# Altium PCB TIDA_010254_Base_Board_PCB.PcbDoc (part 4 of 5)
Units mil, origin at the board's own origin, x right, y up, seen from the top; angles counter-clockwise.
Board outline 3514.38 x 3143.81 mil, 4 copper layers (Top Layer, L2_GND1, L3_PWR1, Bottom Layer), stack 62.715 mil thick; 219 components, 146 nets, 618 pads, 2382 vias.
Unrouted connection lines stored in the file: 2280.
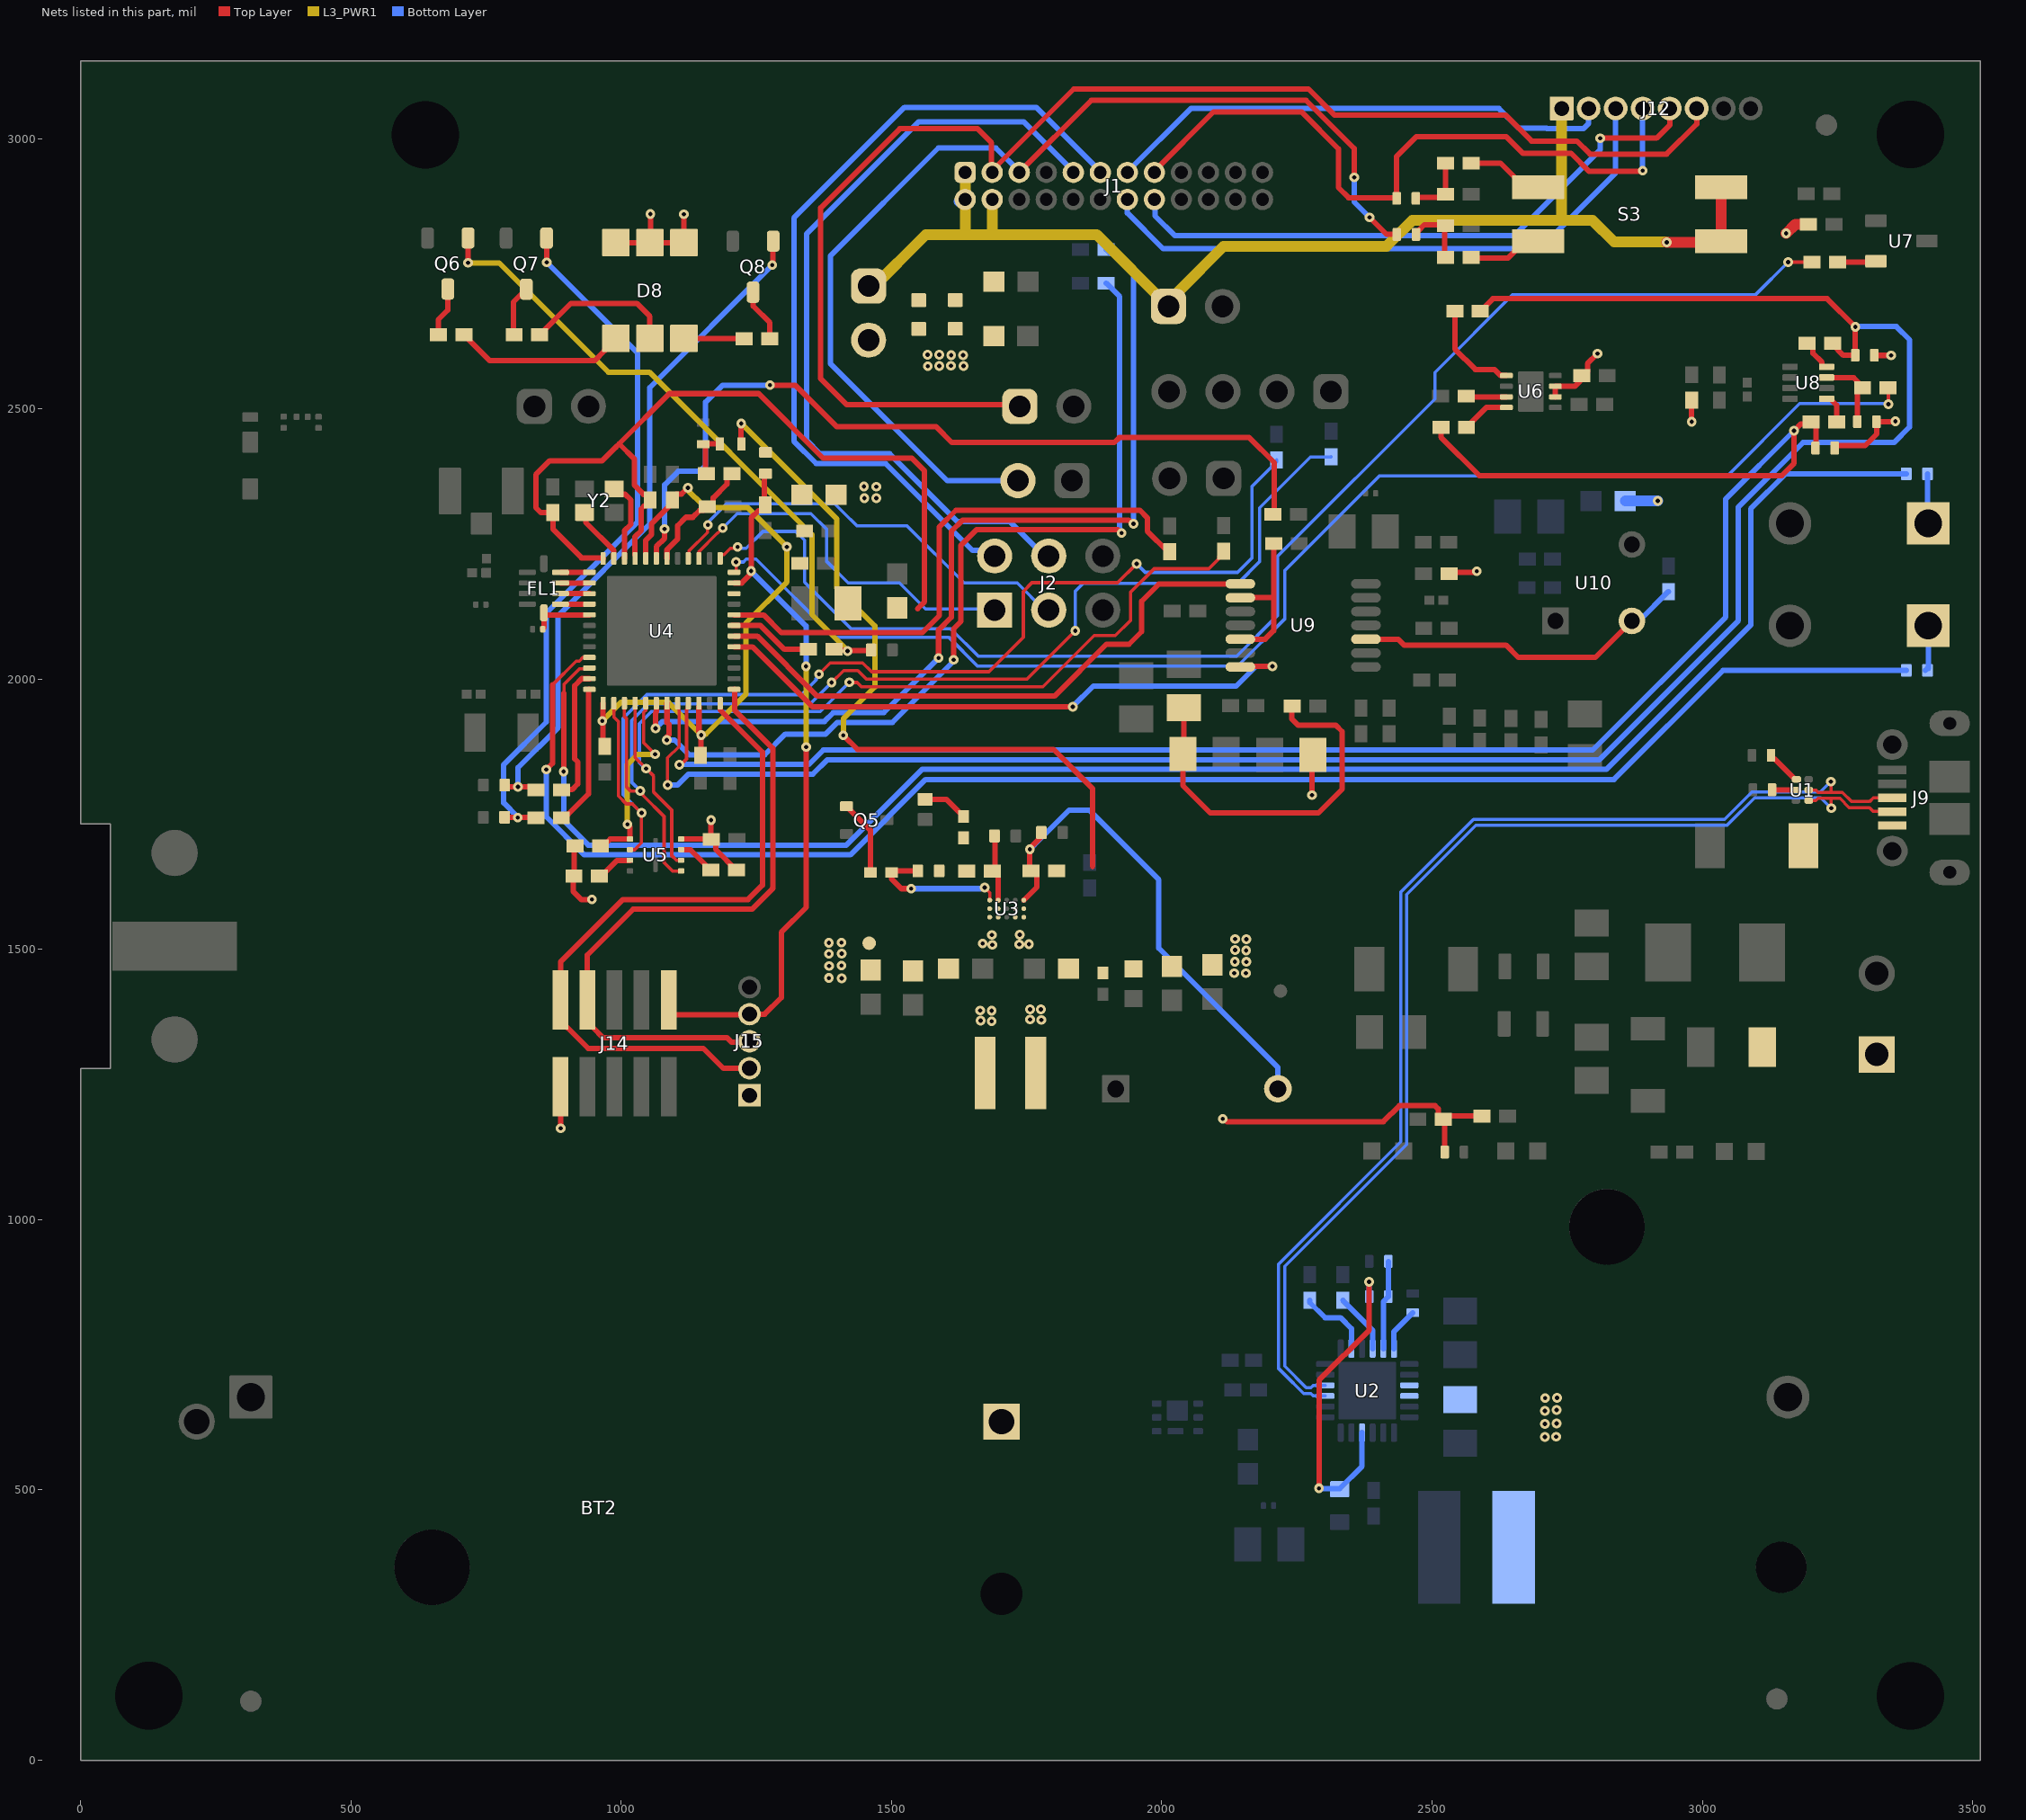
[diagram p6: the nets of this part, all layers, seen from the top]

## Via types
v1: diameter 18, hole 8, Top Layer to Bottom Layer, tented both sides, 2351 vias
v2: diameter 19.68, hole 7.87, Top Layer to Bottom Layer, 21 vias
v3: diameter 19.68, hole 11.81, Top Layer to Bottom Layer, 9 vias
v4: diameter 18, hole 8, Top Layer to Bottom Layer, tented bottom, 1 vias

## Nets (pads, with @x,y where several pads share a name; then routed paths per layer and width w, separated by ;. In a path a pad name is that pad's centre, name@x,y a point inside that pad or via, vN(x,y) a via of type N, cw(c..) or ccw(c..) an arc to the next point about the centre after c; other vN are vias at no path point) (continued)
NetD7_2: D7.2 R23.1 | length 84.5
  Top Layer w10: D7.2@1562.16,1777.8 1601.42,1777.8 R23.1@1633.43,1745.79
NetD8_1: D8.1 R27.2 | length 319.2
  Top Layer w10: R27.2@708.79,2637.27 756.82,2589.24 950.58,2589.24 969.43,2608.09 969.43,2609.84 D8.1@990.02,2630.43
NetD8_2: D8.2 R28.2 | length 278.7
  Top Layer w10: R28.2@849.08,2637.27 907.12,2695.31 1028.77,2695.31 1053.01,2671.07 D8.2@1053.01,2630.43
NetD8_3: D8.3 R29.2 | length 111.8
  Top Layer w10: D8.3@1116.01,2630.43 1116.57,2629.86 R29.2@1227.59,2629.86
NetD10_2: D10.2 J9.1
NetF1_2: F1.2 J8.1
NetFL1_6: FL1.6 U4.4 | length 55.8
  Top Layer w6: U4.4@940.97,2138.67 U4.4@943.41,2138.67
  Top Layer w10: FL1.6@887.6,2138.66 U4.4@940.97,2138.67
NetFL1_7: FL1.7 U4.3 | length 53.4
  Top Layer w10: FL1.7@887.6,2158.34 U4.3@940.97,2158.36
NetFL1_8: FL1.8 U4.2 | length 53.4
  Top Layer w10: FL1.8@887.62,2178.04 U4.2@940.97,2178.04
NetFL1_9: FL1.9 U4.1 | length 53.4
  Top Layer w10: FL1.9@887.6,2197.71 U4.1@940.97,2197.73
NetL4_1: L4.1 U3.B2 U3.B3
  other v1: 1776.93,1369.56 1756.18,1370.51 1756.58,1389.24 1776.26,1389.1 1736.28,1509.25 1754.3,1509.68 1737.07,1527.23
NetL4_2: L4.2 U3.D2 U3.D3
  other v1: 1685.27,1367.02 1664.69,1368.14 1663.75,1387.04 1685.08,1386.47 1686.49,1508.55 1668.69,1510.95 1685.49,1526.78
NetQ5_1: Q5.1 R24.2 | length 140.8
  Top Layer w10: Q5.1@1416.69,1764.8 1460.85,1720.64 R24.2@1460.85,1642.32
NetQ6_1: Q6.1 R25.2 R26.1 | length 1191.1
  Top Layer w6: v1@716.47,2770.4 v1(716.7,2770.17)
  Top Layer w10: v1@716.47,2770.4 Q6.1@716.47,2816.21 ; R25.2@1393.76,2055.14 1394.99,2053.91 1414.54,2053.91 1416.34,2052.11 v1(1418.51,2052.11) ; v1@1421.64,2052.94 R26.1@1455.36,2052.94
  L3_PWR1 w10: v1(716.7,2770.17) 774,2770.17 976.14,2568.03 1052.04,2568.03 1352.96,2267.12 1352.96,2119.06 v1@1418.37,2053.64
NetQ6_3: Q6.3 R27.1 | length 91.7
  Top Layer w10: R27.1@661.55,2637.27 661.55,2664.98 679.07,2682.5 Q6.3@679.07,2721.72
NetQ7_1: Q7.1 R30.2 R31.1 | length 1312.9
  Top Layer w6: R31.1@788.49,1745.06 R31.1@789.11,1744.45 ; v1@808,1744.45 v1(808.65,1743.8) v1@809.27,1744.41 ; R30.2@841.05,1744.41 R30.2@841.91,1743.55 ; Q7.1@861.85,2815.91 Q7.1@862.02,2815.73 ; v1@862.02,2771.31 v1(862.2,2771.13)
  Top Layer w10: R31.1@789.11,1744.45 v1@808,1744.45 ; v1@809.27,1744.41 R30.2@841.05,1744.41 ; v1@862.02,2771.31 Q7.1@862.02,2815.73
  Bottom Layer w6: v1(808.65,1743.8) v1@808.65,1744.83
  Bottom Layer w10: v1@808.65,1744.83 782.48,1771 782.48,1841.79 861.28,1920.59 861.28,2122.26 1030.38,2291.36 1030.38,2602.96 v1@860.17,2773.16
NetQ7_3: Q7.3 R28.1 | length 94.7
  Top Layer w10: R28.1@801.84,2637.27 800.46,2638.65 800.46,2697.44 Q7.3@824.44,2721.42
NetQ8_1: Q8.1 R32.2 R33.1 | length 1255.1
  Top Layer w6: R33.1@784.56,1808.84 784.56,1807.61 R33.1@791.27,1800.9
  Top Layer w10: R33.1@791.27,1800.9 v1(808.87,1800.9) R32.2@831.13,1800.9 ; v1(1279.3,2766.14) 1280.23,2767.08 1280.23,2809.15 Q8.1@1281.16,2810.08
  Bottom Layer w10: v1(808.87,1800.9) 808.87,1836.3 883.08,1910.5 883.08,2117.45 1052.99,2287.36 1052.99,2539.53 v1@1279.3,2765.84
NetQ8_3: Q8.3 R29.1 | length 104.6
  Top Layer w10: Q8.3@1244.18,2721.74 1244.18,2690 1274.83,2659.35 R29.1@1274.83,2629.86
NetR1_2: R1.2 U1.1 | length 67.9
  Top Layer w10: R1.2@3127.1,1859.06 3127.1,1855.12 3129.97,1852.25 3133.91,1852.25 3170.2,1815.96 3170.2,1815.56 3171.1,1814.65 U1.1@3174.06,1814.65
NetR2_2: R2.2 U1.2 | length 44.3
  Top Layer w10: R2.2@3128.98,1795.39 3129.41,1794.97 U1.2@3173.07,1794.97
NetR5_2: R5.2 U2.8 | length 137.9
  Bottom Layer w10: R5.2@2273.73,850.77 2273.73,846.83 2301.95,818.61 2330.54,818.61 2350.67,798.48 U2.8@2350.67,761.52
NetR10_2: R10.2 U2.12 | length 81
  Bottom Layer w10: U2.12@2429.41,761.52 2429.41,793.02 R10.2@2464.41,828.02
NetR13_2: R13.2 U2.10 | length 112.1
  Bottom Layer w10: R13.2@2334.9,850.77 2390.04,795.63 U2.10@2390.04,761.52
NetR14_1: R14.1 R16.2 U2.11 | length 165.2
  Bottom Layer w10: U2.11@2409.72,761.52 2409.72,848.28 R14.1@2419.1,857.67 R16.2@2419.1,922.83
NetR19_1: R19.1 R22.2 U3.D1 | length 122.1
  Top Layer w10: R22.2@1691.81,1708.61 1691.81,1648.03 1689.03,1645.25 1697.44,1636.85 U3.D1@1697.44,1591.15
NetR20_1: R20.1 R21.1 SW1.2 U3.A1 | length 943
  Top Layer w10: U3.A1@1744.68,1591.15 1768.75,1615.21 1768.75,1638.44 1761.94,1645.25 R20.1@1758.13,1645.25 ; R20.1@1755.24,1645.25 1755.24,1686.46 R21.1@1777.39,1708.61
  Bottom Layer w10: v1(1756.02,1685.11) 1763.61,1692.69 1828.62,1757.7 1865.65,1757.7 1994.34,1629.02 1994.34,1502.16 2214.77,1281.72 SW1.2@2214.77,1242.23
NetR34_1: R34.1 R35.2 R36.2 | length 87.9
  Top Layer w6: R36.2@1151.61,2434.44 R36.2@1152.59,2435.42
  Top Layer w10: R36.2@1152.59,2435.42 R34.1@1182.65,2435.42 ; R35.2@1156.13,2372.95 R36.2@1156.13,2429.4
NetR39_2: R39.2 S1.1 | length 84
  Bottom Layer w10: R39.2@3412.59,2016.21 R39.2@3415.7,2019.32 ; R39.2@3417.91,2019.32 S1.1@3417.91,2098.89
NetR40_2: R40.2 S2.1 | length 92.3
  Bottom Layer w10: R40.2@3416.6,2379.92 3416.6,2289.46 S2.1@3417.91,2288.15
NetR43_1: R43.1 U6.3 | length 74.8
  Top Layer w10: R43.1@2563.22,2523.63 2564.61,2522.24 U6.3@2637.49,2522.24
NetR44_2: R44.2 U7.2 | length 71.6
  Top Layer w10: R44.2@3250.05,2771.61 3319.4,2771.61 U7.2@3321,2773.21
NetR45_1: R45.1 R48.1 U8.7 | length 143.9
  Top Layer w10: U8.7@3228.4,2557.71 3279.94,2557.71 3296.49,2541.16 3286.69,2531.36 R45.1@3286.69,2476.3
NetR50_1: R50.1 U5.3 | length 59
  Top Layer w10: R50.1@967.45,1639.95 992.3,1664.8 U5.3@1016.17,1664.8
NetR51_1: R51.1 U5.7 | length 70.7
  Top Layer w10: U5.7@1110.66,1684.48 1128.2,1684.48 R51.1@1165.81,1646.88
NetR55_1: R55.1 R60.2 R61.2 | length 718.3
  Top Layer w10: R61.2@2040.87,1953.63 2040.87,1868.66 2040.87,1863.23 R55.1@2038.91,1861.26 2038.91,1803.38 2089.72,1752.57 2289.82,1752.57 2333.56,1796.3 2333.56,1903.16 2321.68,1915.04 2251.87,1915.04 2240.13,1926.77 R60.2@2240.13,1950.1
NetR57_2: R57.2 U9.9 U9.12 | length 290.4
  Top Layer w10: U9.12@2145.3,2073.94 2191.15,2073.94 2206.95,2089.73 R57.2@2206.95,2250.92 ; U9.9@2145.3,2150.71 2205.46,2150.71 2206.05,2151.29
NetR59_2: R59.2 U9.3 U10.2 | length 624
  Top Layer w10: U9.3@2377.59,2073.94 2437.37,2073.94 2448.18,2063.13 2636.69,2063.13 2659.39,2040.43 2802.2,2040.43 U10.2@2869.5,2107.73
  Bottom Layer w10: U10.2@2869.5,2107.73 2883.03,2107.73 R59.2@2937.32,2162.02
NetR66_1: R66.1 R70.1 R75.2 | length 117.8
  Top Layer w10: R66.1@2467.3,2891.2 2519.22,2891.2 R75.2@2525.21,2897.2 R70.1@2525.21,2954.64
NetR67_2: R67.2 U4.18 | length 1746.1
  Top Layer w10: v1(1063.3,1908.95) 1063.3,1937.65 1064.99,1939.35 U4.18@1064.99,1955.6 ; v1(1587.07,2039.27) 1587.07,2090.88 1610.63,2114.44 1610.63,2273.23 1631.76,2294.36 1938.81,2294.36 v1@1945.53,2287.65
  Bottom Layer w10: v1(1063.3,1908.95) 1076.19,1921.84 1375.88,1921.84 1392.14,1938.1 1485.9,1938.1 v1(1587.07,2039.27) ; R67.2@1897.02,2795.01 1903.83,2788.2 1908.04,2788.2 1947.69,2748.55 v1(1947.69,2287.65)
NetR68_2: R68.2 U4.19 | length 1690
  Top Layer w10: v1(1084.42,1887.56) 1084.42,1893.22 1088.17,1896.97 1088.17,1916.46 1084.67,1919.95 U4.19@1084.67,1955.6 ; v1(1614.85,2035.78) 1614.85,2093.21 1628.63,2106.99 1628.63,2247.92 1657.08,2276.36 1918.86,2276.36 1920.3,2275.59 v1(1925.52,2270.36)
  Bottom Layer w10: v1(1084.42,1887.56) 1098.45,1887.56 1125.7,1860.3 1265.59,1860.3 1303.68,1898.39 1377.98,1898.39 1399.69,1920.1 1501.84,1920.1 1614.85,2033.11 v1(1614.85,2035.78) ; R68.2@1897.02,2732.64 1922.02,2707.64 1922.02,2273.87 v1(1925.52,2270.36)
NetR70_2: R70.2 S3.1 | length 149.7
  Top Layer w10: R70.2@2565.52,2954.85 2626.33,2954.85 2653.34,2927.84 2653.34,2927.29 2670.59,2910.04 S3.1@2696.38,2910.04
NetR71_2: R71.2 U6.4 | length 89.1
  Top Layer w10: R71.2@2563.57,2465.78 2600.36,2502.56 U6.4@2637.49,2502.56
NetR72_2: R72.2 U6.1 | length 185.9
  Top Layer w10: R72.2@2542,2680.9 2542,2610.87 2579.95,2572.91 2615.34,2572.91 2626.64,2561.61 U6.1@2637.49,2561.61
NetR73_1: R73.1 U8.5 | length 45.1
  Top Layer w10: U8.5@3238.62,2516.84 3248.39,2507.08 R73.1@3248.39,2475.81
NetR74_1: R74.1 U8.8 | length 65.6
  Top Layer w10: R74.1@3193.72,2621.55 3197.65,2621.55 3204.46,2614.73 3204.46,2602.95 3221.18,2586.23 3221.18,2578.73 3222.08,2577.83 U8.8@3229.89,2577.83
NetR76_1: R76.1 R77.1 R78.2 | length 122.4
  Top Layer w10: R76.1@2469.69,2824.7 2469.69,2826.14 2473.17,2829.62 2474.61,2829.62 2485.53,2840.53 R78.2@2524.86,2840.53 ; R77.1@2524.86,2780.11 2523.56,2781.41 2523.56,2837.53 R78.2@2524.86,2838.84
NetR77_2: R77.2 S3.2 | length 168.3
  Top Layer w10: R77.2@2566.96,2779.41 2640.63,2779.41 2653.34,2792.12 2653.34,2792.8 S3.2@2670.59,2810.04 ; S3.2@2670.59,2810.04 S3.2@2696.38,2810.04 S3.2@2670.59,2810.04
NetU4_46: U4.46 Y2.3 | length 152.4
  Top Layer w10: Y2.3@987.08,2351.88 996.78,2342.18 1007.3,2342.18 1017.8,2331.68 1017.8,2286.45 1005.93,2274.59 U4.46@1005.93,2223.32
NetU4_47: U4.47 Y2.1 | length 121.9
  Top Layer w6: Y2.1@931.96,2308.57 Y2.1@942,2298.53
  Top Layer w10: Y2.1@931.96,2308.57 934.46,2306.07 934.46,2289.77 986.25,2237.98 U4.47@986.25,2223.32
OPT_INT: R48.2 U4.36 | length 2523.8
  Top Layer w6: U4.36@1208.69,2197.73 1210.87,2197.73 1212.6,2199.45 v1(1212.6,2216.76) ; R48.2@3343.73,2541.16 3344.25,2540.65 v1(3344.25,2508.9)
  Bottom Layer w6: v1(1212.6,2216.76) 1225.84,2216.76 1231.04,2221.96 1249.27,2221.96 1393.52,2077.7 1605.62,2077.7 1659.01,2024.31 2140.13,2024.31 2227.82,2112 2227.82,2201.34 2402.19,2375.71 3045.93,2375.71 3179.9,2509.68 3343.47,2509.68 v1(3344.25,2508.9)
PIR_OUT_HI: U4.29 U9.14 | length 1133.5
  Top Layer w10: U4.29@1208.69,2059.93 1242.55,2059.93 1353.43,1949.05 v1(1835.13,1949.05) ; U9.14@2145.3,2022.76 2146.27,2023.73 v1(2204.41,2023.73) v1@2205.38,2024.7
  Bottom Layer w10: v1(1835.13,1949.05) 1873.23,1987.15 2137.44,1987.15 2174.02,2023.73 v1(2204.41,2023.73)
PIR_OUT_LO: U4.30 U9.8 | length 1101.5
  Top Layer w6: U9.8@2144.64,2175.64 U9.8@2145.3,2176.3
  Top Layer w10: U4.30@1208.69,2079.62 1251.74,2079.62 1362.66,1968.7 1801.62,1968.7 1897.41,2064.49 1939.23,2064.49 1962.59,2087.84 1962.59,2138.57 1962.6,2144.08 1994.16,2175.64 U9.8@2144.64,2175.64
PIR_SIGNAL_ADC: R54.2 U4.43 | length 1578.8
  Top Layer w10: U4.43@1064.99,2223.32 1064.99,2245.29 1080.2,2260.5 v1(1080.2,2277.79) ; v1(1275.01,2543.94) 1321.59,2543.94 1398.8,2466.73 1582.67,2466.73 1611.59,2437.81 1911.94,2437.81 1921.16,2447.04 2161.61,2447.04 2208.09,2400.56 R54.2@2208.09,2303.89
  Bottom Layer w10: v1@1080.37,2277.96 1080.37,2359.62 1105.22,2384.46 1145.14,2384.46 1156.17,2395.49 1156.17,2512.58 1187.52,2543.94 v1(1275.01,2543.94)
PMIC_CLKOUT_LIN_PHY_TX_SOP1: J1.5 J7.2 R76.2 | length 2001.5
  Top Layer w10: J1.5@1736.28,2937.4 1869.81,3070.92 2266.75,3070.92 2356.03,2981.65 v1(2356.03,2928.43) ; v1(2384.33,2854.38) 2415.9,2822.81 R76.2@2434.87,2822.81
  Bottom Layer w10: J7.2@1733.87,2367.31 1603.11,2367.31 1415.42,2555 1386.76,2583.67 1386.76,2782.79 1586.69,2982.72 1692.95,2982.72 J1.5@1736.76,2938.92 ; v1(2356.03,2928.43) 2356.03,2882.68 v1(2384.33,2854.38)
RADAR_3V3: C2.1 FB3.2 FB4.2 J1.1 J1.2 J1.4 J3.1 J4.1 J12.1 S3.3 S3.4 | length 2277.6
  Top Layer w20: v1@2933.91,2808.34 3033.26,2808.34 S3.3@3034.96,2810.04 S3.4@3034.96,2910.04 ; S3.4@3033.7,2910.45 S3.4@3034.1,2910.04
  L3_PWR1 w20: J4.1@1461.08,2719.88 1563.62,2822.42 1636.38,2822.42 ; J1.1@1636.28,2937.4 J1.2@1636.28,2887.4 1636.28,2822.52 1636.38,2822.42 ; J1.4@1686.28,2887.4 1686.28,2823.49 1685.21,2822.42 ; J12.1@2739.56,3055.87 2739.56,2850.47 2738.09,2849 ; v1@2933.61,2808.58 2837.08,2808.58 2796.66,2849 2738.09,2849 ; 1636.38,2822.42 1685.21,2822.42 ; 1685.21,2822.42 1879.49,2822.42 J3.1@2012.34,2689.57 2030.97,2708.2 2030.97,2717.57 2114.35,2800.95 2415.58,2800.95 2463.64,2849 2738.09,2849
  Bottom Layer w10: J3.1@2012.34,2689.57 J3.1@2023.58,2678.33
  Bottom Layer w20: J1.2@1624.63,2883.69 1632.57,2883.69 J1.2@1636.28,2887.4
  other v1: 2933.88,2808.31
RADAR_NRST: J1.3 J12.6 J16.1 | length 2603.4
  Top Layer w10: J1.3@1685.16,2944.57 1685.16,2992.35 1659.29,3018.23 1515.37,3018.23 1368.97,2871.83 1368.97,2555.89 1417.1,2507.77 1734.36,2507.77 J16.1@1737.33,2504.8 ; J1.3@1689.82,2944.57 1837.1,3091.84 2271.29,3091.84 2319.27,3043.86 2635.69,3043.86 2683.99,2995.56 2767.84,2995.56 2792.06,2971.34 2933.96,2971.34 2989.56,3026.93 J12.6@2989.56,3055.87
REG_PG: R24.1 R49.2 U3.E1 | length 268.9
  Top Layer w6: v1(1672.25,1614.47) 1681.69,1605.03 U3.E1@1681.69,1591.15
  Top Layer w10: v1(1536.3,1612.44) 1518.07,1612.44 1500.53,1629.98 1500.53,1642.64 1503.15,1645.25 R49.2@1548.67,1645.25
  Bottom Layer w10: v1(1536.3,1612.44) 1573.66,1612.44 1664.57,1612.44 1665.07,1612.94 1670.72,1612.94 v1(1672.25,1614.47)
REGN: C8.1 R14.2 U2.22 | length 606.9
  Top Layer w10: v1(2290.85,503.02) 2290.85,703.12 2383.67,795.94 v1(2383.67,885.02)
  Bottom Layer w10: v1(2290.85,503.02) 2291.43,502.44 2329.1,502.44 2370.35,543.7 U2.22@2370.35,606 ; R14.2@2383.67,857.67 v1(2383.67,885.02)
RX_TX: C27.2 FL1.5 U4.5 | length 115.6
  Top Layer w6: FL1.5@856.89,2122.71 FL1.5@860.62,2118.99
  Top Layer w10: C27.2@854.81,2093.33 857.34,2095.87 FL1.5@857.34,2122.26 ; FL1.5@860.62,2118.99 U4.5@940.97,2118.99
SPI_CS: R65.2 U4.32 | length 1055.4
  Top Layer w10: U4.32@1208.69,2118.99 1263.29,2118.99 1296.14,2086.13 1556.86,2086.13 1588.48,2117.74 1588.48,2281.75 1619.09,2312.36 1959.6,2312.36 1973.33,2298.64 1973.33,2273.96 2011.44,2235.84 R65.2@2014.57,2235.84
SYS_POWER: BT2.1 C4.1 C12.1 C13.1 C14.1 C43.1 C44.1 L3.2 R7.1 R15.2 R20.2 R34.2 R52.1 U2.15 U2.16 U3.A2 U3.A3 | length 1955.3
  Top Layer w6: R34.2@1221.71,2443.27 R34.2@1222.05,2442.93 ; v1@1221.71,2472.8 v1(1222.05,2473.14)
  Top Layer w10: R34.2@1221.71,2443.27 v1@1221.71,2472.8 ; v1(1410.85,1896.1) 1437.14,1869.81 1799.77,1869.81 1872.22,1797.35 1872.22,1653.35 ; v1(2112.84,1186.64) 2115,1186.64 2120.3,1181.34 2409.87,1181.34 2439.44,1210.91 2505.62,1210.91 2511.48,1205.05 2511.48,1192.59 2515.58,1188.49 R7.1@2522.25,1188.49 ; R52.1@2523.52,1125.11 R7.1@2523.52,1190.76 ; R7.1@2523.52,1191.59 2531.94,1191.59 R15.2@2592.45,1191.59
  L3_PWR1 w10: v1(1222.05,2473.14) 1398.94,2296.25 1398.94,2168.78 1469.15,2098.56 1469.15,1985.46 1410.85,1927.16 v1(1410.85,1896.1)
  other v1: 2708.79,597.96 2729.29,598.55 2708.79,622.32 2730.48,623.21 2708.79,646.38 2730.48,647.87 2709.09,670.15 2731.08,670.45 2133.85,1455.95 2155.62,1455.95 2135.26,1477.25 2156.56,1477.02 2135.72,1499.03 2156.09,1498.32 2135.72,1519.16 2156.56,1518.69
SYS_POWER_ADC: C28.1 R35.1 U4.42 | length 222
  Top Layer w10: U4.42@1084.67,2223.32 1084.67,2239.52 1102.37,2257.21 1102.37,2257.39 1104.2,2259.23 1104.2,2283.99 1119.7,2299.49 1132.27,2299.49 1145.17,2312.39 1152.63,2312.39 C28.1@1159.44,2319.2 1163.38,2319.2 1170.19,2326.01 1170.19,2335.44 1195.38,2360.63 1195.38,2373.36 1202.19,2380.17 R35.1@1204.62,2380.17
USB_D_N: J9.2 U1.4 U2.4 | length 2108.8
  Top Layer w5.8: U1.4@3196.7,1775.28 3209.97,1775.28 3214.31,1779.62 3238.23,1779.62 ; v1@3238.23,1761.26 3238.23,1779.62 ; J9.2@3348.49,1755.17 3316.52,1755.17 3309.22,1762.47 3271.66,1762.47 3254.5,1779.62 3238.23,1779.62
  Bottom Layer w5.8: U2.4@2302.44,693.6 2280.31,693.6 2275.96,689.26 2267.05,689.26 2227.29,729.02 2227.29,913.53 2453.21,1139.46 2453.21,1601.69 2581.04,1729.52 3045.64,1729.52 3048.86,1732.74 3096.47,1780.35 3219.17,1780.35 v1(3238.32,1761.2)
USB_D_P: J9.3 U1.5 U2.3 | length 2144.8
  Top Layer w5.8: U1.5@3196.7,1794.97 3209.97,1794.97 3214.31,1790.62 3238,1790.62 ; v1@3238,1809.32 3238,1790.62 ; J9.3@3348.49,1780.77 3316.52,1780.77 3309.22,1773.47 3276.21,1773.47 3259.06,1790.62 3238,1790.62
  Bottom Layer w5.8: U2.3@2302.44,673.92 2280.31,673.92 2275.96,678.26 2262.49,678.26 2225.37,715.39 2216.29,724.47 2216.29,918.09 2442.21,1144.01 2442.21,1606.25 2576.48,1740.52 3041.08,1740.52 3091.91,1791.35 3218.44,1791.35 v1(3237.59,1810.5)
VCC_3V3: C1.1 C15.1 C16.1 C17.1 C38.1 D8.4 D8.5 D8.6 FB3.1 FB4.1 J4.2 J14.1 J15.1 L6.1 R3.2 R6.2 R19.2 R23.2 R38.2 R41.2 R42.2 R45.2 R46.2 R47.2 R49.1 R50.2 R51.2 R58.1 R63.1 TP1.1 U3.E2 U3.E3 U5.8 U6.6 U6.7 | length 1181.9
  Top Layer w10: v1@887.9,1169.05 J14.1@887.9,1209.64 ; R38.2@914.32,1691.4 912.5,1689.59 R50.2@912.5,1635.68 911.64,1634.82 911.64,1606.8 925.98,1592.46 v1(945.81,1592.46) ; D8.6@990.02,2807.59 D8.5@1053.01,2807.59 ; v1(1053.94,2860.28) 1053.94,2808.52 D8.5@1053.01,2807.59 ; U5.8@1110.66,1704.17 1166.03,1704.17 C38.1@1166.17,1704.03 ; v1(1115.87,2860) 1115.87,2807.73 D8.4@1116.01,2807.59 D8.5@1053.01,2807.59 ; v1@1166.17,1739.09 C38.1@1166.17,1704.03 ; C38.1@1166.59,1703.61 C38.1@1166.17,1704.03 ; C38.1@1168.16,1703.61 1174.97,1696.8 1174.97,1684.95 R51.2@1213.05,1646.88 ; v1(2277.93,1785.54) 2277.93,1858.61 R6.2@2279.51,1860.2 ; R63.1@2523.54,2197.89 2581.02,2197.89 v1(2582.74,2199.61) ; U6.6@2728.04,2522.24 U6.7@2728.04,2541.93 ; U6.7@2728.2,2541.77 2764.11,2541.77 2773.17,2550.84 2773.17,2564.93 2783.97,2564.93 2787.47,2568.43 2787.47,2583.66 v1(2806.02,2602.22) ; v1(2980.19,2476.42) R58.1@2980.19,2515.92 2983.05,2518.78 R58.1@2983.25,2518.78 ; R46.2@3244.12,2432.11 3301.09,2432.11 3322.62,2453.64 R45.2@3322.62,2475.8 ; R47.2@3318.15,2599.26 3318.48,2598.93 v1(3349.11,2598.93) ; R45.2@3322.12,2476.3 3355.94,2476.3 v1@3357,2477.36
  Top Layer w20: v1@3154.94,2824.53 3171.91,2841.49 R42.2@3196.29,2841.49
  Bottom Layer w10: J4.2@1457.5,2627.24 J4.2@1471.17,2627.24 ; R3.2@2857.22,2329.36 R3.2@2857.86,2330.01
  Bottom Layer w20: R3.2@2857.86,2330.01 v1(2917.7,2330.01)
  other v1: 887.87,1169.02 1384.22,1447.08 1408,1446.71 1384.59,1469.38 1407.45,1470.31 1384.22,1491.88 1407.63,1492.06 1384.22,1512.34 1407.45,1512.53 1166.2,1739.12 1449.95,2334.81 1471.93,2334.95 1471.82,2355.93 1449.07,2356.48 3357.2,2477 1567.1,2578.93 1588.54,2579.48 1609.89,2579.66 1633.1,2579.3 1610.24,2599.22 1632.39,2599.14 1588.27,2600.03 1566.84,2600.38 3154.95,2824.99
VDDR: C23.1 C24.1 C25.1 L5.2 U4.45 U4.48 | length 1586.3
  Top Layer w10: C25.1@873.56,2308.29 851.03,2308.29 841.97,2317.35 841.97,2378.19 867.86,2404.08 964.71,2404.08 989.85,2429.22 996.05,2435.42 ; C25.1@873.92,2308.29 873.92,2277.08 926.41,2224.59 965.29,2224.59 U4.48@966.56,2223.32 ; U4.45@1025.58,2230.13 1025.58,2263.56 1036.77,2274.75 1036.77,2314.83 1042.86,2320.92 1046.79,2320.92 1053.6,2327.73 C24.1@1053.6,2331.67 ; C24.1@1054.15,2335.05 1047.3,2341.9 1041.41,2341.9 1024.51,2358.8 1024.51,2406.97 996.05,2435.42 ; 1548.36,2130.52 1561.23,2143.4 1561.23,2385.2 1537.91,2408.52 1373.79,2408.52 1254.07,2528.23 1088.86,2528.23 996.05,2435.42
VDDS: C18.1 C19.1 C20.1 C21.1 C22.1 L6.2 R37.2 U4.13 U4.22 U4.34 U4.44 | length 1207.2
  Top Layer w6: C18.1@964.16,1880.67 C18.1@969.23,1875.6
  Top Layer w10: U4.13@966.29,1955.33 966.29,1924.15 v1(964.93,1922.8) 966.47,1921.27 966.47,1880.77 C18.1@966.56,1880.67 ; U4.44@1045.3,2223.32 1045.3,2256.81 1056.2,2267.71 1056.2,2287.73 1087.76,2319.28 1087.76,2320.76 1089.26,2322.26 C20.1@1090.74,2322.26 ; C20.1@1094.57,2331.51 1094.57,2335.45 1101.38,2342.26 1111.55,2342.26 v1(1123.36,2354.06) ; U4.22@1143.73,1948.79 1143.73,1902.77 1147.75,1898.74 v1(1147.75,1896.58) ; C19.1@1144.51,1860.11 1147.14,1862.74 1147.14,1895.16 v1@1148.65,1896.67
  L3_PWR1 w10: v1(964.93,1922.8) 999.16,1957.03 1087.31,1957.03 v1(1147.75,1896.58) 1149.28,1898.11 1156.68,1898.11 1230.38,1971.81 1230.38,2103.69 1306.51,2179.82 v1(1306.51,2244.75) 1233.69,2317.58 1155.16,2317.58 v1@1119.06,2353.68
WMCU_BLED: R25.1 U4.31 | length 160.7
  Top Layer w6: U4.31@1208.69,2099.3 U4.31@1209.1,2098.89
  Top Layer w10: U4.31@1204.79,2099.79 1257.03,2099.79 1301.8,2055.02 R25.1@1346.4,2055.02
WMCU_FLASH_CLK: R64.2 U4.16 U5.6 | length 1678
  Top Layer w6: U4.16@1025.62,1955.6 1025.62,1855.04 v1(1046.16,1834.5) 1059.99,1820.68 1059.99,1790.98 1093.38,1757.59 1093.38,1673.67 1102.25,1664.8 U5.6@1110.66,1664.8 ; v1@1421.57,1993.81 1436.34,1993.81 1444.37,1985.78 1780.2,1985.78 1874.91,2080.49 1914.18,2080.49 1941.97,2108.28 1941.97,2160.45 1985.8,2204.28 2087.01,2204.28 2105.52,2222.79 2105.52,2226.98 R64.2@2114.38,2235.84
  Bottom Layer w6: v1(1046.16,1834.5) 1044.48,1834.5 1033.44,1845.55 1033.44,1917.73 1055.91,1940.2 1368.09,1940.2 v1(1421.98,1994.09) v1@1425.28,1997.39
WMCU_FLASH_CS: R38.1 U4.17 U5.1 | length 353
  Top Layer w6: v1@1010.84,1732.01 v1(1011.42,1731.44) v1@1016.17,1726.68 ; U4.17@1045.3,1955.6 1045.3,1942.29 1044.99,1941.98 1043.99,1941.98 1043.99,1940.97 1041.3,1938.28 1041.3,1882.38 v1(1062.57,1861.11)
  Top Layer w10: R38.1@971.8,1696.47 979.5,1704.17 U5.1@1016.17,1704.17 v1@1016.17,1726.68
  L3_PWR1 w10: v1(1011.42,1731.44) 1011.42,1842.33 1030.2,1861.11 v1(1062.57,1861.11)
WMCU_FLASH_MISO: R18.2 U4.14 U5.2 | length 2067.7
  Top Layer w6: U4.14@986.25,1955.6 986.25,1929.99 994.86,1921.38 994.86,1783.66 1009.35,1769.17 1020.63,1769.17 v1(1037.42,1752.38) 1037.42,1697.33 1024.58,1684.48 U5.2@1016.17,1684.48 ; v1(1365.77,2009.11) 1386.76,2030.11 1446.64,2030.11 1462.97,2013.78 1680.22,2013.78 1743.81,2077.37 1743.81,2162.5 1759.72,2178.41 1918.36,2178.41 v1(1953.47,2213.52)
  Bottom Layer w6: v1(1037.42,1752.38) 1003.63,1786.17 1003.63,1927.52 1047.51,1971.41 1333.17,1971.41 1360.34,1998.58 1360.34,2000.43 1365.77,2005.87 v1(1365.77,2009.11) ; v1(1953.47,2213.52) 1969.32,2197.67 2139.99,2197.67 2167.07,2224.75 2167.07,2356.86 2203.29,2393.08 2203.42,2393.08 2212.23,2401.89 R18.2@2212.23,2405.83
WMCU_FLASH_MOSI: R17.2 U4.15 U5.5 | length 2121.3
  Top Layer w6: U4.15@1005.93,1955.6 1005.93,1930.52 1010.07,1926.38 1010.07,1800.12 1016.93,1793.26 v1(1035.42,1793.26) 1035.42,1790.02 1040.46,1784.97 1040.46,1784.85 1079.32,1746 1079.32,1660.86 1095.07,1645.11 U5.5@1110.66,1645.11 ; v1(1389.2,1993.78) 1411.52,2016.11 1437.64,2016.11 1453.97,1999.78 1750.14,1999.78 v1(1839.98,2089.62)
  Bottom Layer w6: v1(1035.42,1793.26) 1019.44,1809.24 1019.44,1923.53 1050.11,1954.2 1349.62,1954.2 v1(1389.2,1993.78) ; v1(1839.98,2089.62) 1839.98,2162.64 1854.24,2176.9 2140.56,2176.9 2181.07,2217.41 2181.07,2235.41 ; 2181.07,2235.41 2181.07,2317.09 2274.91,2410.92 2288.44,2410.92 2288.78,2411.27 2313.2,2411.27 R17.2@2313.29,2411.36
WMCU_GLED: R30.1 U4.12 | length 279.7
  Top Layer w6: R30.1@891.13,1741.58 901.91,1752.36 R30.1@902.83,1752.36
  Top Layer w10: R30.1@889.16,1743.55 895.97,1750.36 902.02,1750.36 939.18,1787.52 939.18,1856.19 939.18,1980.92 939.45,1981.19 U4.12@940.97,1981.19
WMCU_REED: R44.1 U4.37 | length 2579.5
  Top Layer w6: U4.37@1183.1,2223.32 1183.1,2228.82 1184.82,2230.54 1190.32,2230.54 1201.98,2242.2 1215.44,2242.2 v1@1215.51,2242.14 ; v1@3159.05,2771.61 R44.1@3202.81,2771.61
  Bottom Layer w6: v1@1215.51,2242.14 1230.87,2242.14 1262.1,2273.36 1323.09,2273.36 1339.35,2257.1 1339.35,2179.45 1425.89,2092.91 1609.4,2092.91 1610.6,2091.7 1611.42,2091.7 1660.55,2042.57 2138.59,2042.57 2213.82,2117.8 2213.82,2226.9 2505.09,2518.17 2505.09,2567.36 2649.26,2711.53 3098.77,2711.53 v1(3158.95,2771.71)
  other v1: 1215.24,2244.63
WMCU_RESET: C32.1 J14.10 J15.4 R37.1 U4.35 | length 1332.4
  Top Layer w6: J14.10@1087.62,1406.57 1087.62,1390.35 J14.10@1099.18,1378.78 ; J15.4@1235.92,1378.78 J15.4@1237.27,1380.13 ; R37.1@1265.06,2378.33 R37.1@1266.92,2380.18
  Top Layer w10: J14.10@1099.18,1378.78 J15.4@1235.92,1378.78 ; U4.35@1208.69,2178.04 1222.76,2178.04 1238.67,2193.96 1238.67,2202.42 v1@1240.21,2203.95 ; J15.4@1237.27,1380.13 1265.38,1380.13 1295.97,1410.72 1295.97,1531.73 1342.24,1578 v1(1342.24,1874.39) ; v1@1240.52,2205.92 1240.52,2298.39 1253.75,2311.62 1259.44,2311.62 1264.45,2316.63 C32.1@1264.45,2322.32 ; C32.1@1265.06,2322.32 R37.1@1265.06,2378.33
  L3_PWR1 w10: v1(1341.77,2023.53) 1341.77,1874.86 v1(1342.24,1874.39)
  Bottom Layer w10: v1@1240.21,2203.65 1240.21,2199.91 1341.77,2098.34 v1(1341.77,2023.53)
  other v1: 1240.16,2199.96
WMCU_RLED: R32.1 U4.11 | length 250.6
  Top Layer w10: R32.1@890,1795.61 909.08,1795.61 919.62,1806.15 919.62,1846.99 913.81,1852.8 913.81,1987.78 926.9,2000.88 U4.11@940.97,2000.88
WMCU_RX: J2.1 U4.39 | length 697.5
  Top Layer w6: U4.39@1143.73,2223.32 1143.73,2235.9 1178.04,2270.2 1178.58,2270.2 v1(1187.82,2279.44)
  Bottom Layer w6: v1(1187.82,2279.44) 1214.58,2306.2 1351.05,2306.2 1380.22,2277.03 1380.22,2217.47 1419.85,2177.85 1514.82,2177.85 1525.48,2167.19 ; 1525.62,2167.34 1563,2129.96 1688.66,2129.96 J2.1@1690.81,2127.82
WMCU_SCL: R46.1 R71.1 R73.2 U4.21 | length 3439.7
  Top Layer w6: v1(1107.7,1841.6) 1110.03,1841.6 1120.89,1852.47 1120.89,1943.28 1122.32,1944.7 1122.32,1953.88 U4.21@1124.04,1955.6
  Top Layer w10: R71.1@2516.47,2465.64 2516.47,2447.66 2587.65,2376.47 3146.75,2376.47 3169.9,2399.63 v1@3169.9,2459.37 ; v1(3169.65,2459.63) 3182.41,2472.39 3205.29,2472.39 R73.2@3211.27,2478.37 ; R46.1@3208.69,2430.86 3209.96,2432.13 R73.2@3209.96,2482.58
  Bottom Layer w10: v1(1107.7,1841.6) 1108.4,1842.3 1347.16,1842.3 1373.9,1869.04 2797.22,1869.04 3043.32,2115.15 3043.32,2333.42 v1@3169.54,2459.63
WMCU_SDA: R47.1 R72.1 R74.2 U4.20 | length 3955.6
  Top Layer w6: v1(1085.7,1804.02) 1085.7,1854.33 1106.89,1875.52 1106.89,1920.61 ; U4.20@1104.36,1955.6 1106.08,1953.88 1106.08,1944.05 1106.86,1943.28 1106.86,1920.64
  Top Layer w10: R72.1@2589.24,2680.9 2612.4,2704.06 3230.67,2704.06 v1(3282.99,2651.74) 3282.86,2651.61 R47.1@3282.86,2600.2 ; R74.2@3240.53,2619.42 3260.69,2599.26 R47.1@3282.72,2599.26
  Bottom Layer w6: v1(3282.99,2651.74) v1@3283.46,2652.21
  Bottom Layer w10: v1(1085.7,1804.02) 1104.06,1804.02 1124.34,1824.3 1354.61,1824.3 1381.35,1851.04 2809.58,1851.04 3066.76,2108.23 3066.76,2318.38 3186.17,2437.79 3354.63,2437.79 3383.23,2466.39 3383.23,2628.03 3359.04,2652.21 v1@3283.46,2652.21
WMCU_SW1: R39.1 U4.9 | length 3025.3
  Top Layer w6: 872.99,1989.51 916.81,2033.34 922.29,2033.34 929.21,2040.25 U4.9@940.97,2040.25
  Top Layer w10: v1@860.68,1832.05 872.99,1844.35 872.99,1989.51
  Bottom Layer w10: v1(861.48,1832.85) 861.48,1745.14 931.53,1675.09 1423.94,1675.09 1563.27,1814.43 2836.61,1814.43 3038.44,2016.26 R39.1@3377.23,2016.26
WMCU_SW2: R40.1 U4.10 | length 3223.5
  Top Layer w6: 894.02,1973.61 894.47,1974.06 894.47,1991.07 922.73,2019.34 939.75,2019.34 U4.10@940.97,2020.56
  Top Layer w10: v1@894.02,1829.71 894.02,1973.61
  Bottom Layer w10: v1(893.46,1829.15) 893.46,1738.62 938.98,1693.09 1416.48,1693.09 1556.43,1833.04 2822.31,1833.04 3089.46,2100.19 3089.46,2315.01 3154.22,2379.77 R40.1@3377.07,2379.77
WMCU_TCK: J14.4 J15.3 U4.25 | length 1232.9
  Top Layer w6: J14.4@937.07,1367.15 J14.4@942.53,1361.69 ; J15.3@1235.87,1328.73 J15.3@1237.27,1330.13
  Top Layer w10: J14.4@937.07,1367.15 937.07,1489.55 1021.92,1574.4 1242.1,1574.4 1279.26,1611.57 1279.26,1611.71 1280.39,1612.84 1280.39,1872.18 1209.59,1942.99 1209.59,1980.92 1209.31,1981.19 U4.25@1208.69,1981.19 ; J14.4@941.9,1361.06 942.77,1361.06 947.18,1356.65 947.18,1355.77 966.56,1336.4 1196,1336.4 1203.68,1328.73 J15.3@1235.87,1328.73
WMCU_TMS: J14.2 J15.2 U4.24 | length 1355.6
  Top Layer w6: J14.2@887.62,1406.57 899.18,1395.07 J14.2@899.18,1353.23
  Top Layer w10: J14.2@887.62,1406.57 887.62,1366.21 897.18,1356.65 898.99,1356.65 938.86,1316.78 1152,1316.78 1188.65,1280.13 J15.2@1237.27,1280.13 ; J14.2@887.62,1406.57 887.69,1477.16 1002.93,1592.4 1234.65,1592.4 1261.26,1619.02 1261.26,1864.85 1183.1,1943.02 U4.24@1183.1,1955.6
WMCU_TX: J2.3 U4.40 | length 799.7
  Top Layer w6: U4.40@1124.04,2223.32 1125.66,2224.94 1125.66,2237.63 1159.38,2271.34 v1@1159.38,2285.04
  Bottom Layer w6: v1@1159.38,2285.04 1159.38,2288.98 1194.89,2324.49 1395.11,2324.49 1409.11,2310.49 1436,2283.59 1528.55,2283.59 1634.27,2177.87 1732.63,2177.87 J2.3@1782.63,2127.87
  other v1: 1160.45,2285.34
XDS_DCA_LP_RS232_RX: J1.9 J2.4 | length 1528.1
  Bottom Layer w10: J2.4@1782.63,2227.87 1719.15,2291.35 1622.15,2291.35 1496.6,2416.9 1495.97,2416.9 1495.72,2417.15 1367.85,2417.15 1343.13,2441.88 1343.13,2824.13 1550.23,3031.23 1744.44,3031.23 J1.9@1836.76,2938.92
XDS_DCA_LP_RS232_TX: J1.11 J2.2 | length 1565.6
  Bottom Layer w10: J2.2@1682.63,2227.87 1672.11,2238.39 1649.65,2238.39 1489.15,2398.9 1360.65,2398.9 1319.4,2440.15 1319.4,2853.2 1524.09,3057.89 1767.79,3057.89 J1.11@1886.76,2938.92
XDS_DCA_TCK: J1.14 J12.3 | length 1132.9
  Bottom Layer w10: J1.14@1936.28,2887.4 1936.28,2862.54 2002.54,2796.28 2699.13,2796.28 2839.56,2936.71 J12.3@2839.56,3055.87
XDS_DCA_TDI: J1.16 J12.5 | length 1125.9
  Top Layer w10: v1(2811.19,3000.74) 2915.25,3000.74 2939.56,3025.04 J12.5@2939.56,3055.87
  Bottom Layer w10: J1.16@1986.28,2887.4 1987.38,2886.3 1987.38,2857.21 2024.25,2820.33 2651.63,2820.33 2811.19,2979.89 v1(2811.19,3000.74)
XDS_DCA_TDO_SOP0: J1.15 J12.4 R66.2 | length 1292.8
  Top Layer w10: J1.15@1986.28,2937.4 1986.28,2940.08 2095.7,3049.5 2258.33,3049.5 2326.98,2980.85 2326.98,2909.28 2345.44,2890.82 R66.2@2434.51,2890.82 ; R66.2@2434.51,2889.44 R66.2@2434.51,2890.82 ; v1@2888.94,2939.79 2790.13,2939.79 2757.01,2972.91 2667.57,2972.91 2636.78,3003.69 2470.91,3003.69 2434.51,2967.3 R66.2@2434.51,2890.82
  Bottom Layer w10: v1(2889.55,2940.78) J12.4@2889.56,3055.87
XDS_DCA_TMS: J1.13 J12.2 | length 948.4
  Bottom Layer w10: J1.13@1936.76,2938.92 2053.71,3055.87 2623.68,3055.87 2660.42,3019.13 2712.15,3019.13 2712.46,3018.82 2780.55,3018.82 2789.56,3027.82 J12.2@2789.56,3055.87
pads on no net: BT2.MH FID1.1 FID2.1 FID3.1 FID4.1 FID5.1 FID6.1 J9.4 J14.7 J17. MH1.1 MH2.1 MH3.1 MH4.1 Q1.0 SH-J1.0 SH-J2.0 U6.9 U8.3 U8.6
copper on no net:
  other v1: 1733.58,3082.88

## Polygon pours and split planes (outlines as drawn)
NetC5_1 on Top Layer "NETC5_1_L01_P106" (solid, pour order 106): 2455.94,1276.92 2376.82,1276.92 2376.82,1262.15 2456.08,1262.15
VCC_3V3 on Top Layer "NONET_L01_P-001" (solid, pour order 118): 1395.25,2666.76 1652.56,2666.76 1660.24,2659.08 1712.29,2659.08 1712.29,2568.34 1395.79,2568.34
NetL4_1 on Top Layer "NONET_L01_P-001" (solid, pour order 113): 1742.04,1202.11 1789.98,1202.11 1789.98,1400.38 1742.04,1400.38
GND on Top Layer "GND_L01_P125" (solid, remove dead copper, pour order 125): 6.7,3149.88 6.7,6.07 3521.05,6.07 3521.06,6.07 3521.06,3149.88
RADAR_3V3 on Top Layer "NONET_L01_P-001" (solid, pour order 123): 1656.54,2986.2 1656.54,2908.23 1708.68,2908.23 1709.67,2907.25 1709.67,2677.22 1394.25,2677.22 1394.25,2848.55 1533.16,2987.47
DCDC_SW on Top Layer "NONET_L01_P-001" (solid, pour order 111): 1197.01,2143.33 1261.21,2143.33 1291.23,2173.35 1369.23,2173.35 1369.23,2104.71 1367.33,2102.81 1301.73,2102.81 1270.41,2134.13 1197.01,2134.13
NetL4_1 on Top Layer "NONET_L01_P-001" (solid, pour order 107): 1724.35,1580.62 1733.76,1580.62 1733.76,1543.09 1769.88,1506.97 1769.88,1500.12 1724.35,1500.12
NetL4_2 on Top Layer "NONET_L01_P-001" (solid, pour order 109): 1692.55,1580.16 1702.07,1580.16 1702.07,1499.58 1658.37,1499.58 1658.37,1513.3 1692.36,1547.29
SYS_POWER on Top Layer "SYS_POWER_L01_P121" (solid, remove dead copper, pour order 121): 1788.62,1659.03 1891.17,1659.03 1891.17,1603.35 1961.95,1532.56 2172.32,1532.56 2172.32,1445.94 2170.34,1443.96 1806.78,1443.96 1806.78,1489.05 1739.78,1556.05 1739.78,1579.98 1750.92,1579.98 1751.03,1579.86 1788.62,1617.45
NetC5_1 on Top Layer "NETC5_1_L01_P108" (solid, pour order 108): 3006.21,1788.04 3006.21,1692.83 3023.87,1692.83 3023.87,1788.04
VCC_3V3 on Top Layer "NONET_L01_P-001" (solid, pour order 119): 1686.44,1581.01 1686.44,1555.68 1632.29,1501.53 1632.29,1432.99 1368.8,1432.99 1368.8,1526.07 1594.87,1526.07 1640.37,1571.58 1640.37,1619.34 1630.27,1629.44 1574.2,1629.44 1574.2,1665.32 1574.43,1665.55 1574.65,1665.32 1615.59,1665.32 1615.59,1719.82 1658.75,1719.82 1658.75,1665.32 1658.75,1599.62 1676.81,1581.01
VDDR on Top Layer "VDDR_L01_P105" (solid, pour order 105): 1549.69,2136.02 1496.55,2136.02 1496.55,2125.66 1549.85,2125.66
NetC5_1 on Top Layer "NONET_L01_P-001" (solid, pour order 124): 2306.93,1245.2 2412.4,1245.2 2412.4,1638.51 3059.77,1638.51 3059.77,1753.11 2388.24,1753.11 2306.93,1671.8
NetD10_2 on Top Layer "NONET_L01_P-001" (solid, pour order 115): 3377.3,1738.92 3156.21,1738.92 3156.21,1648.14 3225,1648.14 3298.79,1721.92 3377.3,1721.92
VDDS on Top Layer "NONET_L01_P-001" (solid, pour order 116): 1252.13,2432.99 1297.14,2432.99 1297.4,2433.25 1355.84,2374.81 1355.84,2239.01 1349.52,2232.7 1349.52,2198.97 1297.67,2198.97 1252.05,2153.36 1196.7,2153.36 1196.82,2163.16 1233.45,2163.56 1296.35,2226.47 1296.35,2394.03 1285.56,2404.82 1285.29,2404.56 1251.6,2404.56
NetL4_2 on Top Layer "NONET_L01_P-001" (solid, pour order 114): 1696.13,1398.24 1696.13,1200.69 1647.54,1200.69 1647.54,1398.36
VDDR on Top Layer "NONET_L01_P-001" (solid, pour order 112): 1392.55,2175.55 1393.46,2174.64 1461.16,2174.64 1480.24,2155.56 1480.7,2156.01 1537.38,2156.01 1537.38,2102.4 1393.46,2102.4
VCC_3V3 on Top Layer "NONET_L01_P-001" (solid, pour order 110): 1375.85,2371.23 1375.85,2315.59 1376.64,2314.8 1490.9,2314.8 1490.9,2371.23
NetF1_2 on Top Layer "NONET_L01_P-001" (solid, pour order 120): 3379.95,1365.63 3149.6,1365.63 3078.27,1365.63 3078.27,1256.54 3085.95,1248.86 3379.95,1248.86
NetC7_1 on Top Layer "NONET_L01_P-001" (solid, pour order 122): 3029.58,1255.93 3029.58,1366.83 2991.96,1404.45 2991.96,1552.47 2881.56,1552.47 2831.56,1502.47 2742.45,1502.47 2730.57,1514.35 2679.02,1514.35 2679.02,1305.44 2930.57,1305.44 2980.08,1255.93
NetD4_2 on Top Layer "NONET_L01_P-001" (solid, pour order 117): 2652.86,1513.18 2494.99,1513.18 2494.99,1409.25 2581.82,1322.42 2582.93,1323.53 2652.86,1323.53
GND on Bottom Layer "GND_L04_P141" (solid, remove dead copper, pour order 141): 0,3143.81 0,0 3514.35,0 3514.35,3143.81
SYS_POWER on Bottom Layer "NONET_L01_P-001" (solid, pour order 138): 2441.31,699.03 2751.57,699.03 2751.57,578.59 2695.54,578.59 2695.54,282.81 2603.9,282.81 2603.9,627.9 2594.21,637.6 2515.47,637.6 2484.73,668.34 2441.09,668.34
NetC11_1 on Bottom Layer "NONET_L01_P-001" (solid, pour order 140): 2903.3,611.05 3221.12,610.1 3221.12,730.43 2904.03,730.43 2844.77,789.68 2492.47,789.68 2441.33,738.54 2441.33,708.41 2808.79,708.41
VCC_3V3 on Bottom Layer "VCC_3V3_L04_P136" (solid, remove dead copper, pour order 136): 1404.75,2652.52 1405.5,2651.78 1655.42,2651.78 1655.42,2558.66 1656.91,2557.17 1449.99,2557.17 1405.12,2602.04 1405.12,2653.27
NetL4_2 on Bottom Layer "NONET_L01_P-001" (solid, pour order 132): 1684.39,1539.71 1646.85,1502.17 1646.85,1357.6 1696.01,1357.6 1696.01,1539.71
NetL4_1 on Bottom Layer "NONET_L01_P-001" (solid, pour order 131): 1741.66,1359.73 1787.21,1359.73 1787.21,1495.26 1741.66,1540.81 1741.47,1540.61 1726.93,1540.61 1726.93,1498.56 1741.66,1483.84
RADAR_3V3 on Bottom Layer "RADAR_3V3_L04_P139" (solid, remove dead copper, pour order 139): 1656.07,2960.77 1592.09,2960.77 1403.43,2772.12 1403.43,2672.36 1656.99,2672.36
NetC47_1 on Bottom Layer "NONET_L01_P-001" (solid, pour order 134): 2814.65,2349.79 2692.63,2349.79 2692.63,2257.85 2705.97,2244.51 2705.97,2138.38 2705.97,2087.45 2741.01,2087.45 2741.01,2263.94 2785.43,2308.36 2814.65,2308.36
NetC5_1 on Bottom Layer "NONET_L01_P-001" (solid, pour order 133): 2318.26,641.61 2319.52,640.36 2319.52,627.09 1973.76,627.09 1973.76,712.07 2063.89,712.07 2063.89,666.11 2175.49,666.11 2201.61,641.58
NetC6_1 on Bottom Layer "NONET_L01_P-001" (solid, pour order 135): 1974.81,614.37 2042.55,614.37 2042.55,590.98 2134.41,590.98 2134.41,618.66 2325.76,618.66 2325.56,623 2336.93,623.24 2337.35,578.58 2197.95,578.58 2179.35,559.97 1974.81,559.97
NetC3_1 on Bottom Layer "NONET_L01_P-001" (solid, pour order 137): 2433.77,622.92 2403.98,622.92 2403.98,571.84 2425.44,550.38 2425.44,472.36 2372.98,472.36 2372.98,377.79 2469.02,281.75 2561.61,281.75 2561.61,508.39 2465.8,508.39 2465.8,590.89
SYS_POWER on L3_PWR1 "SYS_L01_P-001" (solid, pour order 128): 2834.27,698.44 2684.12,698.44 2684.12,578.91 2738.6,524.43 2738.6,266.17 2697.61,230.05 1935.52,230.05 1922.76,242.81 1922.76,978.65 2207.61,1263.5 2207.61,1552.35 2101.63,1552.35 2101.63,1328.28 1785.55,1012.2 1785.55,670.82 1656.6,670.82 1656.6,582.1 1785.55,582.1 1785.55,228.19 1904.47,109.27 2738.6,109.27 2834.27,199.02
GND on L3_PWR1 "GND_L03_P130" (solid, remove dead copper, pour order 130): 1.27,3141.84 1.27,-1.97 3515.62,-1.97 3515.62,3141.84
VCC_3V3 on L3_PWR1 "VCC_3V3_L01_P-001" (solid, remove dead copper, pour order 129): 1431.31,1548 1431.31,1156.25 870.92,1156.25 870.92,1245.08 1303.21,1245.08 1303.21,1566.75 926.05,1566.75 928.8,1679.7 1065.1,1679.7 1065.1,1751.31 1264.81,1751.31 1466.81,1953.31 1466.81,2266.59 1038.64,2694.76 1038.64,2888.78 1340.72,2888.78 1340.72,2653.01 1536.39,2653.01 1536.39,2611.47 3112.43,2613.12 3112.43,2838.99 3172.74,2838.99 3173.33,2608.62 3369.46,2609.17 3370.39,2423.41 2981.96,2423.41 2981.96,2169.53 2488.82,2169.53 2488.82,1774.99 1658.3,1774.99
NetC5_1 on L3_PWR1 "C5_L01_P-001" (solid, pour order 127): 2411.77,1306.22 2299.11,1306.22 2299.11,1205.64 1975.73,882.26 1975.73,667.77 1972.17,664.21 2068.11,664.21 2068.11,827.66 2411.77,1171.32
GND on L2_GND1 "GND_L02_P126" (solid, remove dead copper, pour order 126): 0,3143.81 0,0 3514.35,0 3514.35,3143.81

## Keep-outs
Keep-Out Layer:
  text ".Layer_Name" at -1217.36,-2144.71 h60

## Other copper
Top Layer:
  pour cut-out: 2588.72,2459.41 ccw(c2721.35,2541.7) 2580.3,2608.54 2580.48,2608.92 ccw(c2601.96,2615.41) 2608.46,2593.93 cw(c2721.35,2541.7) 2615.06,2477.08 ccw(c2610.72,2455.07)
  pour cut-out: 0,1934.96 329.31,1934.96 329.31,2332.2 314.08,2332.2 313.89,2371.57 329.31,2371.57 329.31,2418.82 313.89,2418.82 313.89,2458.25 329.31,2458.25 329.31,3142.69 330.43,3143.81 0,3143.81
  pour cut-out: 1741.65,1413.86 1741.65,1186.13 1699.56,1186.13 1699.56,1413.67
  pour cut-out: 1707.33,1585.36 1719,1585.36 1719,1580.39 1707.25,1580.39
  text ".Layer_Name" at -746.51,-282.25 h60
L2_GND1:
  pour cut-out: 2588.72,2459.41 ccw(c2721.35,2541.7) 2580.3,2608.54 2580.48,2608.92 ccw(c2601.96,2615.41) 2608.46,2593.93 cw(c2721.35,2541.7) 2615.06,2477.08 ccw(c2610.72,2455.07)
  pour cut-out: 0,1934.96 329.31,1934.96 329.31,2332.2 329.12,2371.57 329.31,2371.57 329.31,2418.82 329.31,2458.25 329.31,3142.69 330.43,3143.81 0,3143.81
L3_PWR1:
  pour cut-out: 2588.7,2459.37 ccw(c2721.33,2541.66) 2580.28,2608.5 2580.46,2608.88 ccw(c2601.94,2615.38) 2608.44,2593.89 cw(c2721.33,2541.66) 2615.04,2477.04 ccw(c2610.7,2455.04)
  pour cut-out: 0,1934.96 329.31,1934.96 329.31,3142.69 330.43,3143.81 0,3143.81
  text ".Layer_Name" at -746.51,-282.25 h60
Bottom Layer:
  pour cut-out: 2588.76,2459.54 ccw(c2721.39,2541.83) 2580.34,2608.67 2580.52,2609.05 ccw(c2602.01,2615.54) 2608.5,2594.06 cw(c2721.39,2541.83) 2615.1,2477.21 ccw(c2610.77,2455.2)
  pour cut-out: 2561.76,523.67 2561.76,266.58 2561.99,266.81 2603.73,266.81 2603.73,523.59
  pour cut-out: 0,1934.96 329.31,1934.96 329.31,3142.69 330.43,3143.81 0,3143.81
  text ".Layer_Name" at -746.51,-282.25 h60

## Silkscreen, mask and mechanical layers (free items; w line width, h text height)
Top Overlay:
  circle w20: c2769.64,2614.04 r13.87
  lines w6: 2783.07,2672.99 2793.85,2672.99 ; 2783.15,2682.79 2789.07,2682.79 ; 2783.2,2692.3 2793.97,2692.3 ; 2783.46,2652.83 2794.24,2652.83 ; 2783.54,2662.63 2789.46,2662.63 ; 2824.96,2611.19 ccw(c2833.8,2608.65) 2842.65,2611.13 ; 2825.31,2679.97 ccw(c2834.14,2677.43) 2842.99,2679.91 ; 2859.35,2641.11 ccw(c2868.18,2638.57) 2877.04,2641.05
  lines w10: 3035.88,2664.52 3048.88,2664.56 ; 3049.73,2704.64 3058.46,2695.97 ; 3050.56,2623.84 3060.86,2634.21 ; 3092.76,2707.75 3092.76,2717.93 ; 3092.95,2610.67 3092.95,2620.85 ; 3124.85,2633.9 3133.57,2625.23 ; 3125.8,2693.03 3136.1,2703.4 ; 3137.62,2664.18 3150.62,2664.22
  lines w15: 2769.26,2701.92 2769.8,2614.24
  lines w25: 3105.1,2663.88 cw(c3093.17,2663.88) 3105.08,2664.55
  text "RADAR JTAG" at 3138.37,3088.59 h30
  text "RADAR_3V3  VCC_3V3" at 1368.55,2953.38 h25 r270
  text "SOP0" at 2366.8,2938.69 h30
  text "RADAR_3V3 GND" at 1844.77,2762.42 h28
  text "SOP1" at 2371.89,2747.52 h30
  text "FLASH MODE" at 2634.6,2736.28 h28 r90
  text "FUNC MODE" at 3138.17,2736.11 h30 r90
  text "3V3" at 3013.64,2732.76 h25
  text "." at 3444.28,2721.52 h60
  text "." at 3376.51,2720.6 h60
  text "V" at 2845.76,2704.71 h40 r180
  text "V" at 2879.81,2665.85 h40 r180
  text "V" at 2845.42,2635.93 h40 r180
  text "SPI CS CLK MOSI MISO" at 1891.14,2602.82 h25
  text "U" at 3381.93,2595.98 h100
  text "NRST CLK_TP" at 1669.21,2567.42 h25
  text "DEBUG RX  TX" at 670,2564.2 h25
  text "I2C SDA SCL" at 1894.54,2433.85 h25
  text "LIN TX  RX" at 1620.4,2422.79 h25
  text "RS232 TX  RX GND" at 1522.64,2285.32 h25
  text "PG" at 1549.5,1809.87 h30
  text "GND" at 3330.21,1550.51 h30 r90
  text "VCC_3V3" at 1351.93,1543.15 h30
  text "GND" at 2202.44,1450.39 h30
  text "CHARGE" at 2269.62,1170.7 h30
  text "VIN" at 3383.51,1145.35 h30 r90
  text "PG" at 2735.1,1109.57 h30
  text "ON  POWER OFF" at 1879.49,1106.43 h30
  text "DC INPUT" at 3155.89,1102 h28
  text "+" at 2878.46,570.3 h300
  text "-" at 412.11,539.46 h300
  text "TIDA-010254 base board Rev.B" at 1705.8,102.24 h100
  text ".Layer_Name" at -746.51,-282.25 h60
Bottom Overlay:
  text ".Layer_Name" at -683.54,-271.66 h25
Top Paste:
  text ".Layer_Name" at -742.88,-283.18 h60
Bottom Paste:
  text ".Layer_Name" at -1217.36,-2144.71 h60
Top Solder:
  text ".Layer_Name" at -742.88,-283.18 h60
  text ".Layer_Name" at -742.88,-283.18 h60
Bottom Solder:
  text ".Layer_Name" at -1217.36,-2144.71 h60
Drill Guide:
  text ".Layer_Name" at -1217.36,-2144.71 h60
M1 Board Outline:
  the board outline again, w6
  text ".Layer_Name" at -1223.97,-2068.02 h40
M2 Board Dimensions:
  text ".Layer_Name" at -1229.24,-2142.77 h60
M3 3D STEP Top:
  text ".Layer_Name" at -1217.36,-2144.71 h60
M4 3D STEP Bottom:
  text ".Layer_Name" at -1217.36,-2144.71 h60
M5 Assembly Top:
  lines w10: -2086.36,-2216.38 4513.64,-2216.38 ; -2086.36,-2013.05 4515.64,-2013.05 ; -2086.36,-1809.72 -2086.36,-2419.72 1918.64,-2419.72 4515.64,-2419.72 4515.64,-1809.72 -2085.86,-1809.72 -2085.86,-2419.72 -510.36,-2419.72 ; 378.64,-2419.72 378.64,-1809.72 ; 1645.64,-2013.05 1645.64,-1809.72 ; 2485.64,-2013.05 2485.64,-1809.72 ; 3107.64,-2426.22 3107.64,-2223.38
  text "COMPONENTS MARKED 'DNP' SHOULD NOT BE POPULATED." at -1844.89,3357.45 h60
  text "ASSEMBLY VARIANT:" at -1839.8,3253.1 h60
  text ".VariantName" at -824.42,3252.28 h60
  text "PCB VIEWED FROM TOP SIDE" at -2022.86,-1941.88 h60
  text "BOARD #:" at 453.64,-1941.88 h60
  text ".PRJ_Number" at 999.14,-1941.88 h60
  text "REV:" at 1843.64,-1941.88 h60
  text ".PCB_Rev" at 2135.14,-1941.88 h60
  text "SVN REV:" at 2681.64,-1941.88 h60
  text ".VersionControl_RevNumber" at 3187.64,-1941.88 h60
  text "Assembly Layer Top" at -1227.36,-2141.22 h60
  text "TID #:" at 453.64,-2145.22 h60
  text ".TID" at 999.14,-2145.22 h60
  text "PLOT NAME =" at -2022.86,-2350.55 h60
  text ".plot_File_Name" at -1217.36,-2350.55 h60
  text "GENERATED    :" at 455.64,-2350.55 h60
  text ".Print_Date" at 1325.14,-2350.55 h60
  text ".Print_Time" at 2054.14,-2350.55 h60
  text "TEXAS INSTRUMENTS" at 3318.64,-2350.55 h60
M6 Assembly Bottom:
  lines w10: -2086.86,-2013.55 4515.14,-2013.55 ; -2084.86,-2216.88 4515.14,-2216.88 ; -678.86,-2426.72 -678.86,-2223.88 ; -56.86,-2013.55 -56.86,-1810.22 ; 783.14,-2013.55 783.14,-1810.22 ; 2050.14,-2420.22 2050.14,-1810.22 ; 2939.14,-2420.22 4514.64,-2420.22 4514.64,-1810.22 -2086.86,-1810.22 -2086.86,-2420.22 510.14,-2420.22 4515.14,-2420.22 4515.14,-1810.22
  text "COMPONENTS MARKED 'DNP' SHOULD NOT BE POPULATED." at 4512.22,-1587.17 h60
  text ".VariantName" at 3468.22,-1703.17 h60
  text "ASSEMBLY VARIANT:" at 4507.22,-1703.17 h60
  text ".VersionControl_RevNumber" at -758.86,-1942.38 h60
  text "SVN REV:" at -252.86,-1942.38 h60
  text ".PCB_Rev" at 293.64,-1942.38 h60
  text "REV:" at 585.14,-1942.38 h60
  text ".PRJ_Number" at 1429.64,-1942.38 h60
  text "BOARD #:" at 1975.14,-1942.38 h60
  text "PCB VIEWED FROM BOTTOM SIDE" at 4451.64,-1942.38 h60
  text "Assembly Bottom Layer" at 4090.64,-2131.22 h60
  text ".TID" at 1429.64,-2145.72 h60
  text "TID #:" at 1975.14,-2145.72 h60
  text "TEXAS INSTRUMENTS" at -889.86,-2351.05 h60
  text ".Print_Time" at 374.64,-2351.05 h60
  text ".Print_Date" at 1103.64,-2351.05 h60
  text "GENERATED    :" at 1973.14,-2351.05 h60
  text ".plot_File_Name" at 3646.14,-2351.05 h60
  text "PLOT NAME =" at 4451.64,-2351.05 h60
M9 Title Sheet:
  lines w10: 214.14,-2619.72 214.14,-2419.72 ; 214.14,6680.28 214.14,6880.28 ; 2714.14,-2619.72 2714.14,-2419.72 ; 2714.14,6680.28 2714.14,6880.28
  text "1" at -1054.52,6750.28 h70
  text "2" at 1441.14,6750.28 h70
  text ".Layer_Name" at -1208.06,-2151.7 h60
  text "1" at -1054.52,-2549.72 h70
  text "2" at 1441.14,-2549.72 h70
